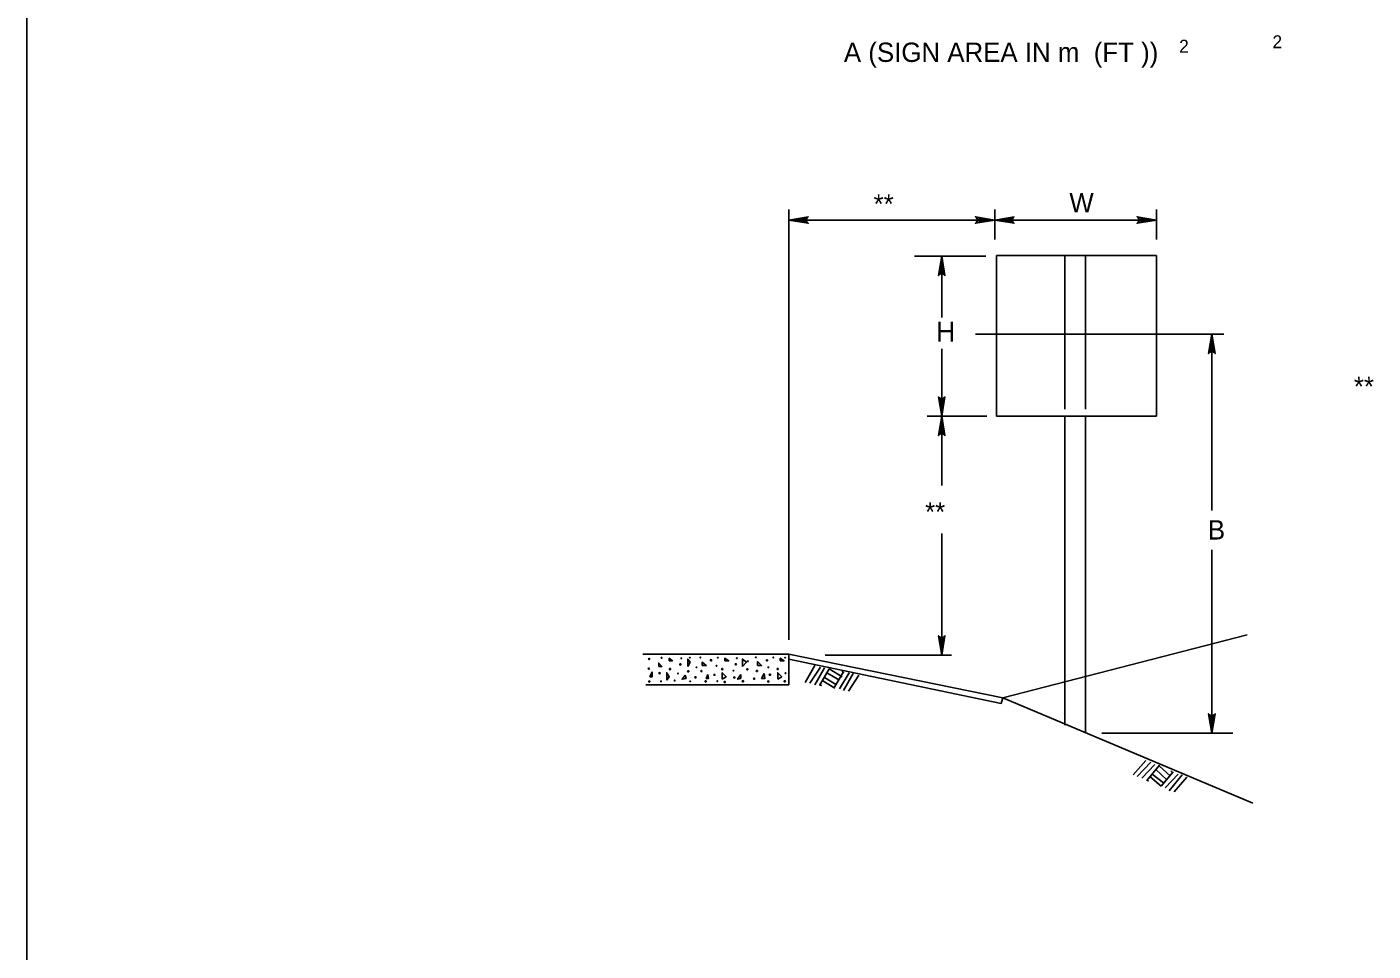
# Model space of a CAD drawing. Extents: x 644358 to 648627, y 294594 to 295782.
# Drawn here: x 645239.3 to 645448.6, y 295485.7 to 295629.3 of the extents above; entities that cross this region are included whole.
import ezdxf

# ---------------------------------------------------------------- set-up
doc = ezdxf.new("R2010")
doc.units = 0
for name, color, linetype in [('1', 7, 'Continuous'), ('2', 7, 'Continuous'), ('3', 7, 'Continuous'), ('4', 7, 'Continuous')]:
    doc.layers.add(name, color=color, linetype=linetype)

# ---------------------------------------------------------------- blocks, each defined once
blk = doc.blocks.new('RARROW')
at = {"layer": '3'}
blk.add_lwpolyline([(-2.2695, 0.285), (-2.184875, 0.12075), (0, 0), (-2.2695, 0.285), (-2.38575, 0.384625), (0, 0), (-2.183125, -0.108), (-2.262875, -0.2705), (0, 0), (-2.38575, -0.379125), (-2.262875, -0.2705)], dxfattribs=at)

msp = doc.modelspace()

# ---------------------------------------------------------------- linework, layer by layer
at = {"layer": '1'}
for p, q in [((645239.31, 295766.63), (645239.31, 295202.63)), ((645361.81, 295530.04), (645360.31, 295527.41)), ((645362.69, 295529.79), (645361.06, 295527.29)), ((645363.31, 295529.66), (645361.81, 295527.04)), ((645364.06, 295529.54), (645362.56, 295526.91)), ((645365.19, 295527.04), (645363.31, 295528.16)), ((645365.69, 295527.79), (645363.69, 295528.91)), ((645366.06, 295528.29), (645364.06, 295529.54)), ((645366.31, 295529.04), (645364.81, 295526.54)), ((645367.19, 295528.91), (645365.69, 295526.41)), ((645366.31, 295528.91), (645366.06, 295529.16)), ((645367.81, 295528.79), (645366.31, 295526.16)), ((645368.69, 295528.54), (645367.06, 295526.04)), ((645362.94, 295526.91), (645362.56, 295527.04)), ((645364.94, 295526.54), (645363.06, 295527.66)), ((645413.31, 295515.29), (645411.31, 295513.04)), ((645414.06, 295515.04), (645411.94, 295512.79)), ((645414.69, 295514.66), (645412.69, 295512.54)), ((645415.44, 295514.54), (645413.44, 295512.16)), ((645416.56, 295512.29), (645414.81, 295513.91)), ((645417.06, 295512.91), (645415.44, 295514.41)), ((645417.56, 295513.54), (645415.69, 295511.29)), ((645417.44, 295513.41), (645417.19, 295513.66)), ((645413.69, 295512.04), (645413.44, 295512.29)), ((645415.69, 295511.29), (645413.94, 295512.79)), ((645416.06, 295511.79), (645414.31, 295513.16)), ((645418.31, 295513.16), (645416.31, 295511.04)), ((645418.94, 295513.04), (645416.94, 295510.54)), ((645419.69, 295512.66), (645417.69, 295510.41))]:
    msp.add_line(p, q, dxfattribs=at)
for points in [[(645337.56, 295529.91), (645337.56, 295530.41), (645338.06, 295529.91)], [(645339.19, 295530.79), (645339.19, 295531.16), (645339.69, 295530.79)], [(645342.06, 295529.91), (645342.06, 295531.04), (645342.44, 295530.54)], [(645344.31, 295530.04), (645344.31, 295530.54), (645344.94, 295530.04)], [(645347.81, 295530.79), (645347.81, 295531.16), (645348.44, 295530.79)], [(645350.56, 295529.91), (645350.56, 295531.04), (645351.19, 295530.54)], [(645352.94, 295530.04), (645352.94, 295530.66), (645353.56, 295530.04)], [(645356.44, 295530.79), (645356.44, 295531.16), (645357.06, 295530.79)], [(645336.56, 295529.04), (645336.56, 295528.29), (645336.19, 295528.29)], [(645338.81, 295527.79), (645338.81, 295528.91), (645339.19, 295528.29)], [(645341.69, 295528.54), (645341.81, 295528.04), (645341.19, 295527.91)], [(645345.19, 295528.66), (645345.31, 295528.04), (645344.94, 295528.04)], [(645347.44, 295527.91), (645347.44, 295528.91), (645348.06, 295528.29)], [(645350.31, 295528.66), (645350.31, 295528.04), (645349.81, 295527.91)], [(645353.94, 295528.79), (645354.06, 295528.04), (645353.56, 295528.04)], [(645356.06, 295527.91), (645356.06, 295528.91), (645356.69, 295528.29)]]:
    msp.add_lwpolyline(points, close=True, dxfattribs=at)
for centre, radius in [((645336.07, 295531.05), 0.0979), ((645338, 295531.23), 0.056), ((645340.92, 295530.21), 0.0979), ((645341.08, 295531.17), 0.056), ((645342.4, 295531.26), 0.056), ((645344.02, 295531.29), 0.056), ((645345.7, 295530.86), 0.0979), ((645346.75, 295531.26), 0.056), ((645349.55, 295530.24), 0.0979), ((645349.7, 295531.19), 0.056), ((645351.42, 295530.73), 0.056), ((645352.65, 295531.31), 0.056), ((645354.39, 295530.85), 0.0979), ((645355.38, 295531.28), 0.056), ((645357.22, 295531.25), 0.056), ((645336.01, 295529.55), 0.0979), ((645337.69, 295528.85), 0.0979), ((645339.31, 295529.49), 0.0979), ((645340.56, 295528.81), 0.056), ((645342.15, 295529.14), 0.0979), ((645343.28, 295528.22), 0.0979), ((645343.44, 295529.77), 0.056), ((645344.2, 295529.17), 0.0979), ((645346.23, 295528.59), 0.0979), ((645346.55, 295529.99), 0.056), ((645347.43, 295529.48), 0.0979), ((645349.18, 295529.23), 0.056), ((645349.33, 295528.18), 0.0979), ((645351.34, 295529.45), 0.0979), ((645352.4, 295528), 0.0979), ((645352.83, 295529.19), 0.0979), ((645354.61, 295529.76), 0.056), ((645354.85, 295528.61), 0.0979), ((645356.05, 295529.5), 0.0979), ((645357.26, 295528.86), 0.056), ((645336.1, 295527.55), 0.0979), ((645337.91, 295527.58), 0.056), ((645340.03, 295527.7), 0.056), ((645342.45, 295527.58), 0.056), ((645344.85, 295527.57), 0.0979), ((645346.66, 295527.61), 0.056), ((645347.82, 295527.48), 0.0979), ((645350.65, 295527.6), 0.0979), ((645354.61, 295527.56), 0.0979), ((645357.15, 295527.58), 0.0979)]:
    msp.add_circle(centre, radius, dxfattribs=at)
at = {"layer": '2'}
for p, q in [((645390.06, 295593.79), (645390.06, 295568.79)), ((645414.94, 295593.79), (645390.06, 295593.79)), ((645400.69, 295593.79), (645400.69, 295569.91)), ((645403.94, 295593.79), (645403.94, 295569.91)), ((645414.94, 295568.79), (645414.94, 295593.79)), ((645390.06, 295568.79), (645414.94, 295568.79)), ((645400.69, 295568.66), (645400.69, 295520.79)), ((645403.94, 295568.79), (645403.94, 295519.54)), ((645391.06, 295525.04), (645429.06, 295534.79)), ((645357.81, 295531.79), (645335.06, 295531.79)), ((645357.81, 295531.79), (645357.81, 295527.04)), ((645357.81, 295531.79), (645391.06, 295525.04)), ((645357.81, 295531.04), (645390.81, 295524.16)), ((645357.81, 295527.04), (645335.56, 295527.04)), ((645391.06, 295525.04), (645390.81, 295524.16)), ((645391.06, 295525.04), (645429.94, 295508.66))]:
    msp.add_line(p, q, dxfattribs=at)
at = {"layer": '4'}
for p, q in [((645357.81, 295600.91), (645357.81, 295534.04)), ((645389.81, 295599.29), (645357.81, 295599.29)), ((645389.81, 295600.91), (645389.81, 295596.29)), ((645414.94, 295599.29), (645389.81, 295599.29)), ((645414.94, 295600.91), (645414.94, 295596.29)), ((645388.44, 295593.66), (645377.31, 295593.66)), ((645381.56, 295593.66), (645381.56, 295584.16)), ((645425.44, 295581.54), (645386.81, 295581.54)), ((645423.56, 295581.54), (645423.56, 295554.16)), ((645381.56, 295579.29), (645381.56, 295568.79)), ((645388.56, 295568.79), (645379.31, 295568.79)), ((645381.56, 295568.79), (645381.56, 295558.04)), ((645381.56, 295550.54), (645381.56, 295531.66)), ((645423.56, 295548.04), (645423.56, 295519.54)), ((645383.06, 295531.66), (645363.44, 295531.66)), ((645426.81, 295519.54), (645406.44, 295519.54))]:
    msp.add_line(p, q, dxfattribs=at)

# ---------------------------------------------------------------- block references
at = {"layer": '2', "xscale": 1.2574347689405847, "yscale": 1.3092961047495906}
for p, rotation in [((645357.81, 295599.29), 180), ((645389.81, 295599.29), 180), ((645381.56, 295593.66), 89.99999999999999), ((645423.56, 295581.54), 89.99999999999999), ((645381.56, 295568.79), -90.00000000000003), ((645381.56, 295568.79), 89.99999999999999), ((645381.56, 295531.66), -90.00000000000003), ((645423.56, 295519.54), -90.00000000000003)]:
    msp.add_blockref('RARROW', p, dxfattribs=dict(at, rotation=rotation))
for p in [(645389.81, 295599.29), (645414.94, 295599.29)]:
    msp.add_blockref('RARROW', p, dxfattribs=at)

# ---------------------------------------------------------------- texts
at = {"layer": '4'}
for s, height, p in [('A (SIGN AREA IN m  (FT ))', 3.005, (645366.35, 295623.87)), ('2', 2, (645418.49, 295625.32)), ('2', 2, (645433, 295626.01)), ('W', 3, (645401.41, 295600.49)), ('**', 3, (645370.97, 295600.3)), ('H', 3.09, (645380.69, 295580.41)), ('** SEE SHEET 9 OF 9 FOR SIGN LOCATION/INSTALLATION   ', 3, (645445.65, 295571.92)), ('**', 3, (645378.98, 295552.43)), ('B', 3, (645422.95, 295549.63))]:
    msp.add_text(s, height=height, dxfattribs=at).set_placement(p)

doc.saveas('drawing.dxf')
